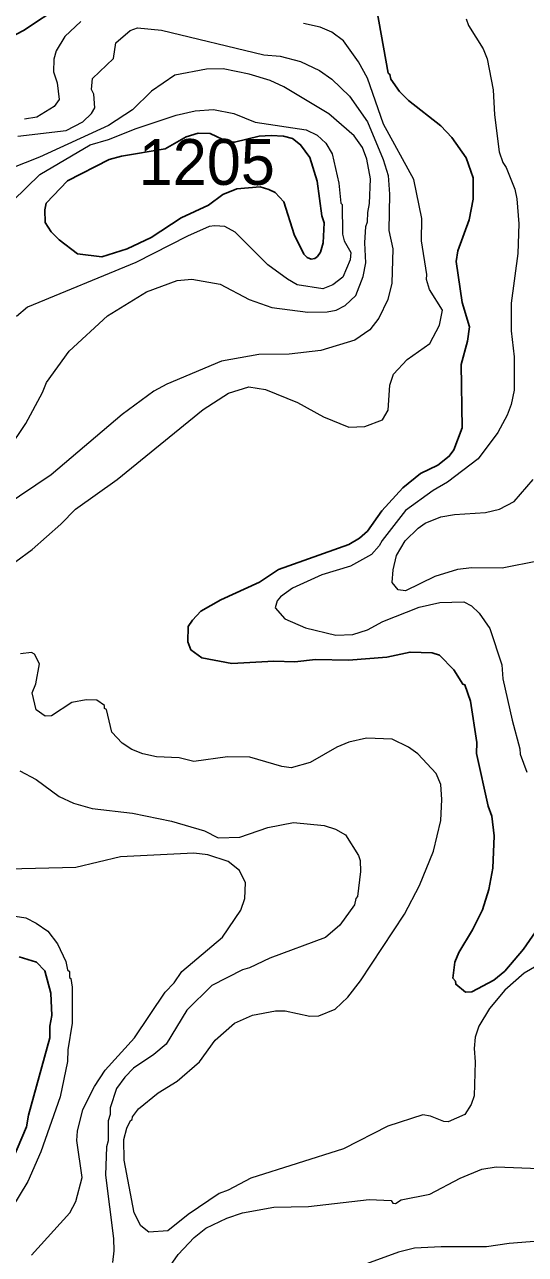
# Model space of a CAD drawing. Extents: x 598.3 to 623.2, y 6902.2 to 6930.1.
# Drawn here: x 600.179 to 601.055, y 6923.743 to 6925.891 of the extents above; entities that cross this region are included whole.
import ezdxf

# ---------------------------------------------------------------- set-up
doc = ezdxf.new("R2010")
doc.units = 0
doc.header["$LTSCALE"] = 0.032
doc.layers.add('1', color=7, linetype='Continuous', lineweight=25)
doc.layers.add('2', color=7, linetype='Continuous', lineweight=13)
doc.layers.add('21', color=7, linetype='Continuous')

msp = doc.modelspace()

# ---------------------------------------------------------------- linework, layer by layer
at = {"layer": '1'}
for points in [[(600.2444, 6925.9254), (600.1777, 6925.8811), (600.1419, 6925.8623), (600.1229, 6925.8402), (600.1201, 6925.8286), (600.1197, 6925.7999), (600.1034, 6925.7871), (600.0838, 6925.7874), (600.0511, 6925.7965), (599.9943, 6925.8293), (599.9616, 6925.8436), (599.8998, 6925.8388), (599.8629, 6925.8284), (599.8253, 6925.8243), (599.8073, 6925.8169), (599.7774, 6925.7957), (599.7254, 6925.7439), (599.6474, 6925.6253), (599.6146, 6925.5795), (599.5732, 6925.528), (599.5543, 6925.5153), (599.5332, 6925.5132), (599.5228, 6925.5236)], [(600.9327, 6924.2205), (600.9279, 6924.2259), (600.9314, 6924.2538), (600.9383, 6924.2707), (600.962, 6924.31), (600.9795, 6924.3452), (600.9908, 6924.3803), (600.9974, 6924.4179), (600.9999, 6924.4745), (600.9959, 6924.5086), (600.9894, 6924.5264), (600.9692, 6924.6183), (600.9699, 6924.6371), (600.9586, 6924.7096), (600.9488, 6924.7378), (600.9455, 6924.739), (600.9297, 6924.7645), (600.9043, 6924.7897), (600.8914, 6924.7938), (600.8531, 6924.7954), (600.8122, 6924.7866), (600.7456, 6924.7809), (600.6879, 6924.7824), (600.6517, 6924.7785), (600.6151, 6924.7792), (600.5418, 6924.7753), (600.4889, 6924.7851), (600.4697, 6924.7995), (600.4649, 6924.8133), (600.4652, 6924.8397), (600.4726, 6924.8511), (600.4874, 6924.8665), (600.5226, 6924.8863), (600.5901, 6924.9175), (600.6232, 6924.9393), (600.7459, 6924.9832), (600.7649, 6924.9942), (600.7789, 6925.0067), (600.8037, 6925.0421), (600.8403, 6925.0821), (600.8711, 6925.107), (600.9014, 6925.1218), (600.9215, 6925.1373), (600.9293, 6925.1489), (600.944, 6925.1872), (600.9425, 6925.2976), (600.9534, 6925.3384), (600.957, 6925.3634), (600.944, 6925.4061), (600.9336, 6925.4777), (600.9364, 6925.4962), (600.9566, 6925.5502), (600.9634, 6925.5868), (600.9631, 6925.624), (600.9512, 6925.6586), (600.926, 6925.6942), (600.9066, 6925.7144), (600.8501, 6925.7588), (600.8347, 6925.7749), (600.8195, 6925.796), (600.8177, 6925.8045), (600.8146, 6925.8069), (600.7944, 6925.9203)], [(601.0891, 6924.3311), (601.051, 6924.2762), (601.0185, 6924.2377), (600.9997, 6924.2222), (600.9612, 6924.2017), (600.9498, 6924.2014), (600.933, 6924.2149), (600.9327, 6924.2205)], [(600.1499, 6923.8888), (600.1829, 6923.9658), (600.1864, 6923.9862), (600.2236, 6924.1216), (600.2237, 6924.1417), (600.2268, 6924.1605), (600.2252, 6924.1996), (600.2148, 6924.2382), (600.2001, 6924.2537), (600.1702, 6924.2628)]]:
    msp.add_lwpolyline(points, dxfattribs=at)
msp.add_lwpolyline([(600.5008, 6925.5758), (600.5257, 6925.5944), (600.5505, 6925.6047), (600.591, 6925.6079), (600.6062, 6925.6035), (600.6173, 6925.5979), (600.6326, 6925.5816), (600.6503, 6925.525), (600.6675, 6925.4904), (600.673, 6925.4845), (600.68, 6925.482), (600.6867, 6925.4831), (600.6915, 6925.4864), (600.6967, 6925.4938), (600.7009, 6925.5104), (600.7028, 6925.545), (600.6991, 6925.5572), (600.6907, 6925.6179), (600.678, 6925.6593), (600.6617, 6925.6816), (600.6477, 6925.6923), (600.6316, 6925.6964), (600.6102, 6925.698), (600.5895, 6925.6964), (600.5461, 6925.686), (600.5355, 6925.686), (600.5035, 6925.7013), (600.4826, 6925.702), (600.4616, 6925.6956), (600.4248, 6925.6745), (600.3486, 6925.6617), (600.3272, 6925.6559), (600.2541, 6925.6185), (600.2172, 6925.5798), (600.2148, 6925.568), (600.2155, 6925.5458), (600.2256, 6925.5294), (600.2396, 6925.5152), (600.2716, 6925.4913), (600.3143, 6925.486), (600.3589, 6925.4995), (600.4004, 6925.5193), (600.4529, 6925.5541)], close=True, dxfattribs=at)
at = {"layer": '2'}
for points in [[(600.2778, 6925.8971), (600.2497, 6925.8705), (600.2348, 6925.8457), (600.2304, 6925.8312), (600.2301, 6925.809), (600.2365, 6925.7895), (600.2397, 6925.7606), (600.2312, 6925.7487), (600.201, 6925.7296), (600.1793, 6925.7263)], [(600.9512, 6925.9015), (600.9554, 6925.8901), (600.9807, 6925.8489), (600.9877, 6925.8319), (600.9983, 6925.7776), (601.0008, 6925.7339), (601.0089, 6925.6695), (601.015, 6925.6508), (601.0208, 6925.6416), (601.036, 6925.6042), (601.0395, 6925.5871), (601.0429, 6925.5434), (601.0411, 6925.4914), (601.0299, 6925.4051), (601.0299, 6925.3567), (601.0348, 6925.3108), (601.0347, 6925.2531), (601.0299, 6925.228), (601.0228, 6925.2089), (601.0062, 6925.1789), (600.9722, 6925.133), (600.9183, 6925.0921), (600.8936, 6925.0778), (600.845, 6925.0427), (600.8043, 6924.9902), (600.7993, 6924.9809), (600.7854, 6924.9655), (600.749, 6924.9456), (600.699, 6924.9302), (600.6478, 6924.9071), (600.6264, 6924.8921), (600.621, 6924.8851), (600.6171, 6924.8725), (600.6343, 6924.8536), (600.6702, 6924.8376), (600.7232, 6924.8251), (600.753, 6924.8261), (600.7784, 6924.834), (600.8056, 6924.8488), (600.8691, 6924.8738), (600.9052, 6924.882), (600.9471, 6924.8828), (600.9604, 6924.8762), (600.9739, 6924.8634), (600.9926, 6924.8367)], [(600.1674, 6925.6966), (600.2518, 6925.7067), (600.2814, 6925.7216), (600.2964, 6925.7361), (600.3021, 6925.746), (600.3005, 6925.7701), (600.2965, 6925.7782), (600.2981, 6925.7975), (600.335, 6925.8321), (600.3391, 6925.8596), (600.3639, 6925.8813), (600.3769, 6925.8858), (600.4185, 6925.8816), (600.5974, 6925.8389), (600.6262, 6925.8365), (600.6613, 6925.8273), (600.6945, 6925.8115), (600.7163, 6925.7963), (600.7473, 6925.7667), (600.7788, 6925.7218), (600.806, 6925.6558), (600.8145, 6925.6276), (600.8169, 6925.5955), (600.8162, 6925.5319), (600.8227, 6925.4997), (600.821, 6925.4398), (600.8139, 6925.4112), (600.7985, 6925.3786), (600.7829, 6925.358), (600.7563, 6925.3404), (600.6972, 6925.3221), (600.6419, 6925.316), (600.5889, 6925.3151), (600.5234, 6925.3038), (600.4282, 6925.2636), (600.4055, 6925.2513), (600.3497, 6925.2105), (600.2257, 6925.105), (600.0879, 6925.0125)], [(600.763, 6925.8263), (600.7366, 6925.8633), (600.7161, 6925.8784), (600.6958, 6925.8868), (600.667, 6925.8932)], [(600.1493, 6925.1469), (600.1817, 6925.1948), (600.2105, 6925.2485), (600.2178, 6925.2663), (600.2574, 6925.3212), (600.3243, 6925.3825), (600.3922, 6925.4246), (600.4461, 6925.4444), (600.4715, 6925.447), (600.5213, 6925.4382), (600.572, 6925.4113), (600.6114, 6925.3974), (600.6744, 6925.3889), (600.7083, 6925.3897), (600.7237, 6925.3928), (600.7398, 6925.4008), (600.7581, 6925.4184), (600.7709, 6925.4514), (600.7756, 6925.4754), (600.7741, 6925.51), (600.7757, 6925.5385), (600.7789, 6925.5467), (600.779, 6925.5634), (600.7821, 6925.5788), (600.7838, 6925.6222), (600.7773, 6925.6565), (600.7697, 6925.6765), (600.7556, 6925.697), (600.7112, 6925.7356), (600.6327, 6925.7829), (600.6087, 6925.7941), (600.572, 6925.8048), (600.5263, 6925.8145), (600.4975, 6925.8138), (600.4419, 6925.8034), (600.4014, 6925.7753), (600.3679, 6925.7427), (600.3262, 6925.7153), (600.2054, 6925.6599), (600.1297, 6925.6301)], [(600.1347, 6924.9327), (600.1924, 6924.9745), (600.2427, 6925.0188), (600.2685, 6925.0451), (600.3414, 6925.0969), (600.4912, 6925.2192), (600.5358, 6925.2478), (600.5715, 6925.2584), (600.6003, 6925.2538), (600.6562, 6925.2316), (600.7017, 6925.2063), (600.7463, 6925.1881), (600.774, 6925.1896), (600.8049, 6925.2012), (600.8145, 6925.2181), (600.8177, 6925.2615), (600.824, 6925.2806), (600.8482, 6925.3066), (600.8878, 6925.3342), (600.9044, 6925.3666), (600.9099, 6925.3928), (600.887, 6925.429), (600.8818, 6925.4461), (600.8824, 6925.4549), (600.8729, 6925.5138), (600.8737, 6925.5526), (600.8599, 6925.6209), (600.8068, 6925.7174), (600.7787, 6925.7982), (600.763, 6925.8263)], [(600.1587, 6925.5836), (600.2063, 6925.6299), (600.2941, 6925.6814), (600.3259, 6925.6908), (600.3742, 6925.7101), (600.4445, 6925.7334), (600.4776, 6925.7409), (600.5097, 6925.7433), (600.5453, 6925.7362), (600.5823, 6925.7212), (600.6715, 6925.7079), (600.6904, 6925.6982), (600.706, 6925.6842), (600.7167, 6925.6658), (600.7287, 6925.6143), (600.7323, 6925.5796), (600.7344, 6925.5771), (600.7349, 6925.5255), (600.7379, 6925.5138), (600.7496, 6925.4931), (600.7481, 6925.4803), (600.7355, 6925.45), (600.7181, 6925.4366), (600.7004, 6925.4301), (600.656, 6925.437), (600.6386, 6925.4467), (600.6044, 6925.4717), (600.5474, 6925.5286), (600.5294, 6925.5386), (600.5116, 6925.5401), (600.5021, 6925.5385), (600.4643, 6925.5221), (600.374, 6925.4761), (600.1842, 6925.3977), (600.1654, 6925.3813)], [(601.0785, 6924.9549), (601.014, 6924.942), (600.9607, 6924.9427), (600.9362, 6924.9396), (600.8965, 6924.9271), (600.8453, 6924.9023), (600.8324, 6924.904), (600.8219, 6924.9169), (600.8236, 6924.939), (600.8292, 6924.9638), (600.8443, 6924.9895), (600.867, 6925.0118), (600.8793, 6925.0204), (600.907, 6925.0315), (600.9305, 6925.0358), (600.9848, 6925.0392), (601.0093, 6925.0452), (601.0352, 6925.0582), (601.068, 6925.0969)], [(600.9926, 6924.8367), (601.0135, 6924.7731), (601.0153, 6924.7486), (601.0312, 6924.6766), (601.0451, 6924.626), (601.0453, 6924.6171), (601.0571, 6924.5855)], [(600.5462, 6924.1473), (600.5779, 6924.1609), (600.6181, 6924.1688), (600.6348, 6924.1688), (600.6778, 6924.159), (600.6938, 6924.1597), (600.722, 6924.1712), (600.7441, 6924.1924), (600.7667, 6924.2208), (600.8431, 6924.3372), (600.8695, 6924.3874), (600.8938, 6924.4476), (600.9068, 6924.5008), (600.9084, 6924.5375), (600.9068, 6924.5639), (600.8987, 6924.5833), (600.8667, 6924.6177), (600.8504, 6924.6294), (600.822, 6924.6429), (600.7771, 6924.6448), (600.7458, 6924.6378), (600.7253, 6924.6294), (600.6783, 6924.6026), (600.6454, 6924.5931), (600.6292, 6924.5953), (600.5733, 6924.6116), (600.5339, 6924.6123), (600.4753, 6924.6044), (600.4494, 6924.6108), (600.4098, 6924.6124), (600.3859, 6924.6178), (600.3666, 6924.6252), (600.3499, 6924.6361), (600.3316, 6924.6552), (600.3224, 6924.6947), (600.3193, 6924.6968), (600.3188, 6924.7017), (600.3056, 6924.7114), (600.287, 6924.7121), (600.2622, 6924.7073), (600.2266, 6924.6837), (600.2152, 6924.6836), (600.1994, 6924.6943), (600.1929, 6924.724), (600.1992, 6924.7398), (600.2057, 6924.775), (600.1968, 6924.7914), (600.1912, 6924.7945), (600.1721, 6924.7922)], [(600.1708, 6924.588), (600.1996, 6924.5727), (600.2397, 6924.5431), (600.2651, 6924.5312), (600.2975, 6924.5219), (600.368, 6924.5137), (600.436, 6924.4999), (600.4938, 6924.483), (600.5178, 6924.4709), (600.5553, 6924.4717), (600.6044, 6924.4887), (600.6492, 6924.4975)], [(600.6492, 6924.4975), (600.7028, 6924.4926), (600.7228, 6924.486), (600.7402, 6924.4763), (600.7631, 6924.44), (600.7659, 6924.4312), (600.7667, 6924.4117), (600.7611, 6924.3684), (600.758, 6924.3648), (600.7562, 6924.3537), (600.7301, 6924.3184), (600.7055, 6924.2966), (600.6079, 6924.2605), (600.5723, 6924.2436), (600.5601, 6924.24), (600.5064, 6924.213), (600.4631, 6924.1695), (600.4271, 6924.1102), (600.4052, 6924.0922), (600.3695, 6924.0685), (600.3543, 6924.0528), (600.34, 6924.0327), (600.3289, 6923.9992), (600.3288, 6923.9877), (600.3257, 6923.9765), (600.3256, 6923.9417), (600.3224, 6923.9309), (600.3208, 6923.8813), (600.3345, 6923.7709), (600.3353, 6923.7491), (600.3329, 6923.7288)], [(600.2583, 6923.8157), (600.2689, 6923.8354), (600.2802, 6923.8775), (600.2706, 6923.942), (600.2721, 6923.9582), (600.2811, 6923.996), (600.3015, 6924.0364), (600.3201, 6924.0647), (600.3716, 6924.1215), (600.425, 6924.2011), (600.4407, 6924.2177), (600.4544, 6924.2371), (600.5253, 6924.2973), (600.5571, 6924.3445), (600.5644, 6924.3648), (600.5652, 6924.3923), (600.5552, 6924.4135), (600.5349, 6924.4292), (600.4999, 6924.4409), (600.4751, 6924.4441), (600.3469, 6924.4377), (600.2692, 6924.4191), (600.1515, 6924.4158)], [(600.1369, 6924.338), (600.1813, 6924.3308), (600.1995, 6924.3219), (600.2202, 6924.3075), (600.2372, 6924.2857), (600.2512, 6924.2545), (600.2544, 6924.2404), (600.2576, 6924.2375), (600.2577, 6924.2266), (600.2601, 6924.225), (600.2624, 6924.21), (600.2625, 6924.1469), (600.2551, 6924.1006), (600.2543, 6924.0799), (600.2415, 6924.0186), (600.2078, 6923.9222), (600.1852, 6923.8704), (600.1565, 6923.8231)], [(601.1008, 6924.2621), (601.0526, 6924.2343), (601.0189, 6924.2049), (600.9921, 6924.1726), (600.9733, 6924.1417), (600.9669, 6924.1225), (600.9651, 6924.1028), (600.9668, 6924.0793), (600.965, 6924.0202), (600.96, 6924.0049), (600.9488, 6923.9875), (600.9194, 6923.9746), (600.9119, 6923.975), (600.8885, 6923.9845), (600.8752, 6923.9867), (600.8139, 6923.9669), (600.7366, 6923.9275), (600.5748, 6923.8765), (600.5349, 6923.8554), (600.5195, 6923.8496), (600.465, 6923.8129), (600.4299, 6923.7844), (600.3965, 6923.7819), (600.3824, 6923.7932), (600.3711, 6923.8154), (600.3532, 6923.9077), (600.3531, 6923.9436), (600.358, 6923.9633), (600.3645, 6923.9768), (600.3675, 6923.9787), (600.368, 6923.9831), (600.3782, 6923.9973), (600.4128, 6924.0255), (600.4459, 6924.0456), (600.4851, 6924.0792), (600.5127, 6924.1173), (600.5462, 6924.1473)], [(600.4104, 6923.6895), (600.4478, 6923.7431), (600.4759, 6923.7728), (600.4964, 6923.7886), (600.533, 6923.8066), (600.5603, 6923.8159), (600.6148, 6923.8256), (600.6758, 6923.8268), (600.7815, 6923.8387), (600.8199, 6923.837), (600.8227, 6923.8323), (600.8273, 6923.8322), (600.8373, 6923.8386), (600.8874, 6923.8485), (600.9403, 6923.8764), (600.9783, 6923.8921), (601.0033, 6923.8962), (601.0787, 6923.8929)], [(600.1914, 6923.7416), (600.2583, 6923.8157)], [(601.0921, 6923.7671), (601.0264, 6923.7619), (600.9867, 6923.7561), (600.9072, 6923.7561), (600.8605, 6923.7537), (600.8329, 6923.7471), (600.7771, 6923.7268)]]:
    msp.add_lwpolyline(points, dxfattribs=at)

# ---------------------------------------------------------------- texts
at = {"layer": '21'}
msp.add_text('1205', height=0.08, dxfattribs=at).set_placement((600.3788, 6925.6115))

doc.saveas('drawing.dxf')
